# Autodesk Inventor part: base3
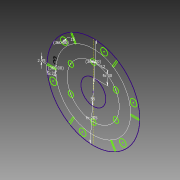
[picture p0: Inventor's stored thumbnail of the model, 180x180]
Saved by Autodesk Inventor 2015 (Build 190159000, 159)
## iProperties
Created: 2017-04
Part Number: base3
Material: Generic
Document SubType Name: Modeling
Designer: mcalderon
Density: 1 g/cm^3
Appearance: Default
Author: mcalderon
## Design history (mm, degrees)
sketch "Sketch1" dims "d0" = 55
  geometry: L1 (82.497, 3.899)-(102.426, 3.899); L2 (102.496, 0.95)-(82.496, 0.95); L3 (82.496, 0.95)-(82.497, 3.899); L4 (37.872, 73.394)-(47.836, 90.653); L5 (50.425, 89.239)-(40.425, 71.918); L6 (40.425, 71.918)-(37.872, 73.394); L7 (-44.625, 69.495)-(-54.589, 86.754); L8 (-52.07, 88.289)-(-42.07, 70.968); L9 (-42.07, 70.968)-(-44.625, 69.495); L10 (-82.497, -3.899)-(-102.426, -3.899); L11 (-102.496, -0.95)-(-82.496, -0.95); L12 (-82.496, -0.95)-(-82.497, -3.899); L13 (-37.872, -73.394)-(-47.836, -90.653); L14 (-50.425, -89.239)-(-40.425, -71.918); L15 (-40.425, -71.918)-(-37.872, -73.394); L16 (44.625, -69.495)-(54.589, -86.754); L17 (52.07, -88.289)-(42.07, -70.968); L18 (42.07, -70.968)-(44.625, -69.495); L19 (0, 102.5)-(0, -102.5); L20 (0, 57.5)-(0, 27.5); L21 (78.609, 25.346)-(89.865, 25.346); L22 (89.865, 25.346)-(89.865, 9.714); L23 (89.865, 9.714)-(78.609, 9.714); L24 (78.609, 9.714)-(78.609, 25.346); C1 r 6 at (0, 57.5); C2 r 6 at (-49.796, 28.75); C3 r 6 at (-49.796, -28.75); C4 r 6 at (0, -57.5); C5 r 6 at (49.796, -28.75); C6 r 6 at (49.796, 28.75); C7 r 7.5 at (65.09, 64.954); C8 r 7.5 at (-23.707, 88.847); C9 r 7.5 at (-88.797, 23.893); C10 r 7.5 at (-65.09, -64.954); C11 r 7.5 at (23.707, -88.847); C12 r 7.5 at (88.797, -23.893); A1 r 102.5 centre (0, 0) between (102.5, 0) and (102.426, 3.899); 2 further points
  constraints: 40 end point, 13 centre point, 5 point on circle, 2 coincident, 2 point on line, 1 horizontal, 1 parallel, 1 vertical, 1 vertical alignment, 73 other
  dimensions: "d1" = 205 diameter of A1 (computed from space); "d2" = 20 distance of L2.start L2.end (= 0.5 x space); "d3" = 2.95 distance of L1.end L2.start; "d6" = 360 deg dimension on point (0, 0) L1.start (derived); "d8" = 12 diameter of C1; "d9" = 30 distance of L20.end L20.start (= 0.75 x space); "d12" = 360 deg dimension on point (0, 0) L20.start (derived); "d14" = 15 diameter of C7; "d17" = 360 deg dimension on point (0, 0) C7.centre (derived)
